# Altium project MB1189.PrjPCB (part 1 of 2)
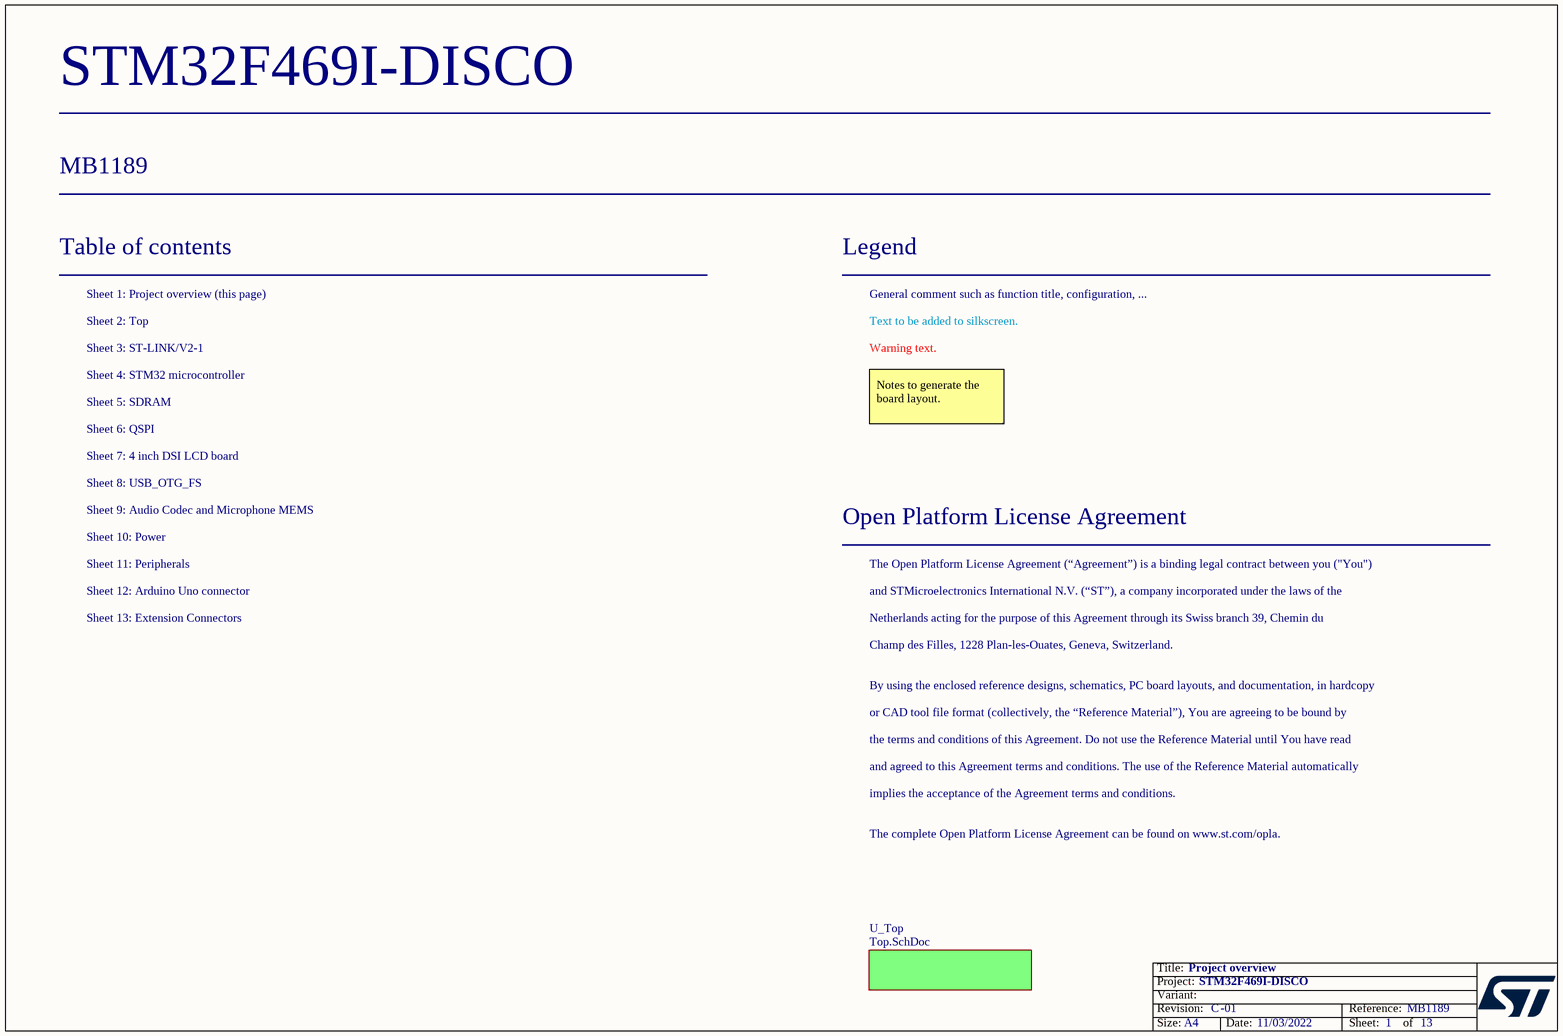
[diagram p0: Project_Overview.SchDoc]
Board_Reference: MB1189; Board_PCB_Revision: C; Board_Name: STM32F469I-DISCO; Board_Document_Date: 11/03/2022; Board_Assembly_revision: 01
13 sheets, 276 parts. Net scope: flat (ports and power ports of the same name join across sheets).
Board file: MB1189.PcbDoc
Sheets:
  Project_Overview.SchDoc
    U_Top = Top.SchDoc
      U_Memory = Memory.SchDoc
      U_Peripherals = Peripherals.SchDoc
      U_Power = Power.SchDoc
      U_ST_LINK_V2-1 = ST_LINK_V2-1.SCHDOC
      U_MCU = MCU.SchDoc
      U_Arduino_ Connectors = Arduino_ Connectors.SchDoc
      U_DSI_LCD = DSI_LCD.SchDoc
      U_QSPI = QSPI.SchDoc
      U_AUDIO2 = AUDIO2.SchDoc
      U_USB_OTG_FS = USB_OTG_FS.SchDoc
      U_ExtensionConnector = ExtensionConnector.SchDoc

## Sheet Project_Overview.SchDoc: Project overview
size A4; Date: Not used; ApprovedBy: Not used; CheckedBy: Not used; Author: Not used; CompanyName: STMicroelectronics; DrawnBy: Not used; Engineer: Not used; Organization: Not used; Address1: Not used; Address2: Not used; Address3: Not used; Address4: Not used; DocumentNumber: MB1189; Revision: Not used; SheetNumber: 1; SheetTotal: 13

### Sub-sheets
U_Top = Top.SchDoc: no entries

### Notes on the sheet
- Table of contents
- Sheet 1: Project overview (this page)
- Legend
- General comment such as function title, configuration, ...
- Sheet 2: Top
- Sheet 3: ST-LINK/V2-1
- Sheet 4: STM32 microcontroller
- Text to be added to silkscreen.
- Warning text.
- Sheet 5: SDRAM
- Sheet 6: QSPI
- Notes to generate the board layout.
- Sheet 7: 4 inch DSI LCD board
- Sheet 9: Audio Codec and Microphone MEMS
- Sheet 8: USB_OTG_FS
- Sheet 10: Power
- Sheet 11: Peripherals
- Open Platform License Agreement
- The Open Platform License Agreement (“Agreement”) is a binding legal contract between you ("You")
- Sheet 12: Arduino Uno connector
- Sheet 13: Extension Connectors
- and STMicroelectronics International N.V. (“ST”), a company incorporated under the laws of the
- Netherlands acting for the purpose of this Agreement through its Swiss branch 39, Chemin du
- Champ des Filles, 1228 Plan-les-Ouates, Geneva, Switzerland.
- By using the enclosed reference designs, schematics, PC board layouts, and documentation, in hardcopy
- or CAD tool file format (collectively, the “Reference Material”), You are agreeing to be bound by
- the terms and conditions of this Agreement. Do not use the Reference Material until You have read
- and agreed to this Agreement terms and conditions. The use of the Reference Material automatically
- implies the acceptance of the Agreement terms and conditions.
- The complete Open Platform License Agreement can be found on www.st.com/opla.

## Sheet Top.SchDoc: MB1189
size A3; Date: 9/24/2014; Author: P.A.; CompanyName: STMicroelectronics; Organization: Microcontrollers Division; Address1: 12, Rue Jules HOROWITZ; Address2: 38019 Grenoble; Address3: FRANCE; DocumentNumber: MB1189; Revision: B-07; SheetNumber: 2; SheetTotal: 13; Project: STM32F469I-DISCO
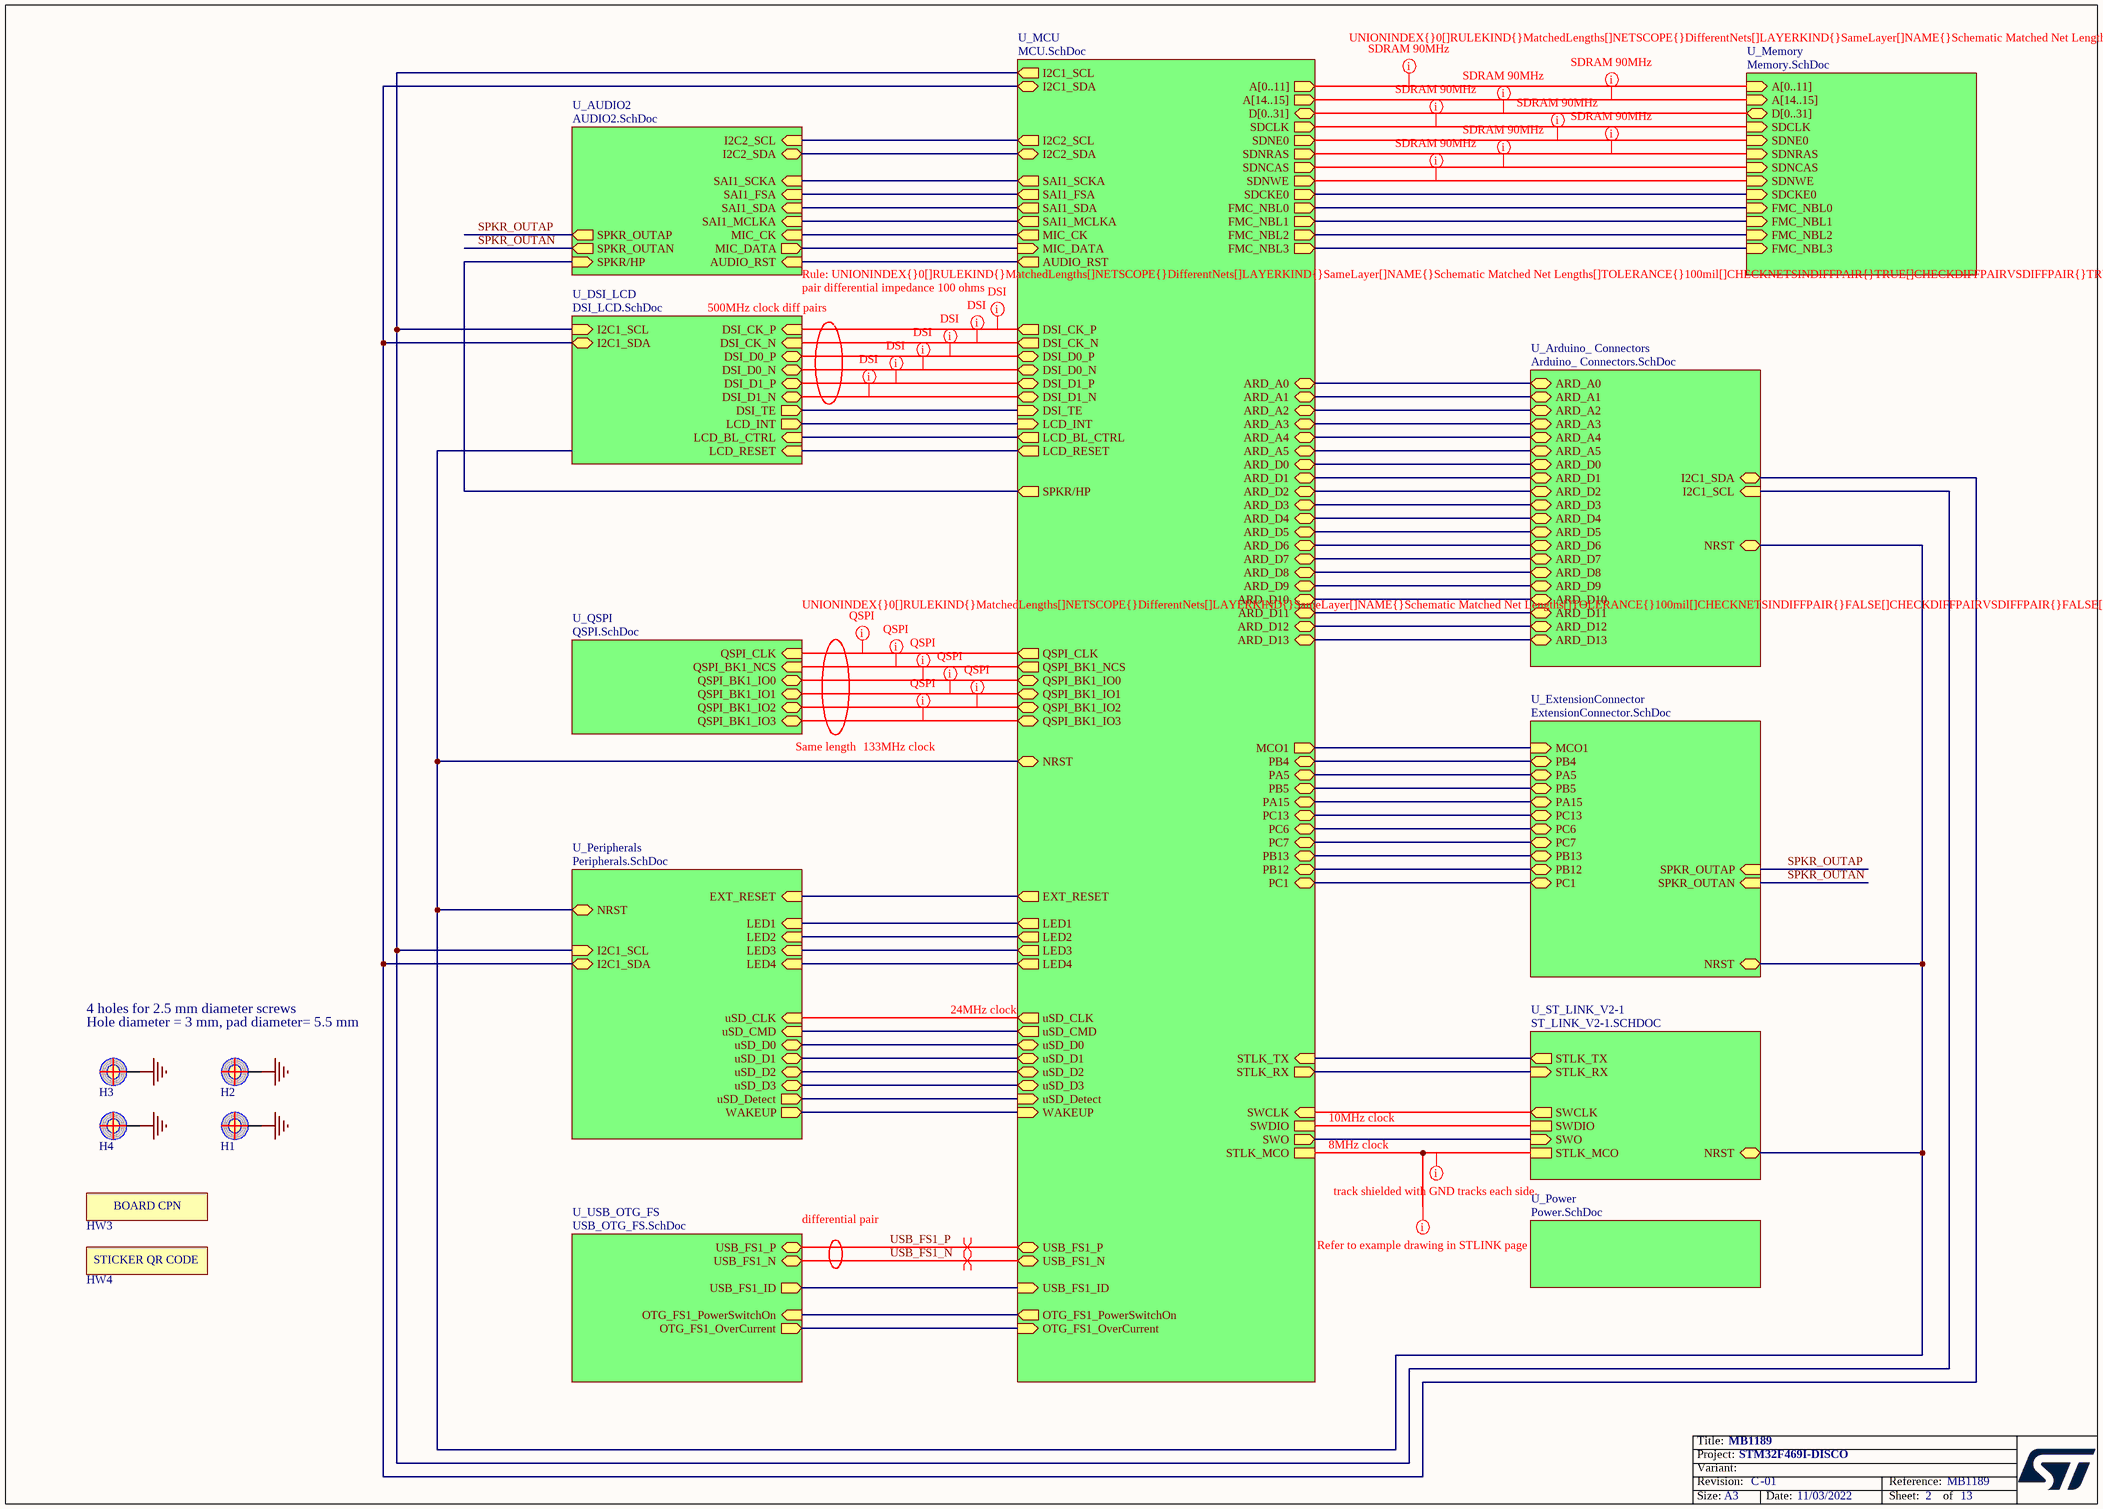
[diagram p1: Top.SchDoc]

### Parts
H1  POSITION HOLE  [HOLE_C5R5D3]  (value not drawn)
H2  POSITION HOLE  [HOLE_C5R5D3]  (value not drawn)
H3  POSITION HOLE  [HOLE_C5R5D3]  (value not drawn)
H4  POSITION HOLE  [HOLE_C5R5D3]  (value not drawn)
HW3  STICKER_BOARD_CPN  [STICKER_BOARD-CPN_13X3]  (value not drawn)  (no BOM)
HW4  STICKER_QR_CODE  [STICKER_QR_CODE_8X8]  (value not drawn)  (no BOM)

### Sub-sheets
U_Arduino_ Connectors = Arduino_ Connectors.SchDoc: I2C1_SDA (bidir), ARD_A0 (bidir), ARD_A1 (bidir), ARD_A2 (bidir), ARD_A3 (bidir), ARD_A4 (bidir), ARD_A5 (bidir), ARD_D5 (bidir), ARD_D4 (bidir), ARD_D3 (bidir), ARD_D2 (bidir), ARD_D1 (bidir), ARD_D0 (bidir), ARD_D13 (bidir), ARD_D12 (bidir), ARD_D11 (bidir), ARD_D10 (bidir), ARD_D9 (bidir), ARD_D8 (bidir), ARD_D6 (bidir), ARD_D7 (bidir), I2C1_SCL (in), NRST (bidir)
U_AUDIO2 = AUDIO2.SchDoc: SAI1_SCKA (in), SAI1_FSA (in), SAI1_SDA (in), AUDIO_RST (in), SAI1_MCLKA (in), I2C2_SCL (in), I2C2_SDA (bidir), MIC_CK (in), MIC_DATA (out), SPKR_OUTAP (out), SPKR_OUTAN (out), SPKR/HP (in)
U_DSI_LCD = DSI_LCD.SchDoc: DSI_CK_P (in), DSI_CK_N (in), DSI_D0_P (bidir), DSI_D0_N (bidir), DSI_D1_P (bidir), DSI_D1_N (bidir), DSI_TE (out), I2C1_SDA (bidir), I2C1_SCL (in), LCD_BL_CTRL (in), LCD_INT (out), LCD_RESET (in)
U_ExtensionConnector = ExtensionConnector.SchDoc: SPKR_OUTAP (in), SPKR_OUTAN (in), NRST (bidir), MCO1 (in), PB4 (bidir), PA5 (bidir), PB5 (bidir), PA15 (bidir), PC13 (bidir), PC7 (bidir), PC6 (bidir), PB13 (bidir), PB12 (bidir), PC1 (bidir)
U_MCU = MCU.SchDoc: LCD_BL_CTRL (out), MIC_CK (out), I2C1_SCL (out), I2C1_SDA (bidir), uSD_D0 (bidir), uSD_D1 (bidir), uSD_D2 (bidir), EXT_RESET (out), uSD_D3 (bidir), uSD_CLK (out), uSD_CMD (out), FMC_NBL3 (out), FMC_NBL2 (out), FMC_NBL0 (out), FMC_NBL1 (out), SAI1_SDA (out), SAI1_SCKA (out), SAI1_FSA (out), SAI1_MCLKA (out), SDNRAS (out), SDCLK (out), SDNCAS (out), SDCKE0 (out), SDNE0 (out), SDNWE (out), D[0..31] (bidir), QSPI_CLK (out), QSPI_BK1_NCS (out), QSPI_BK1_IO3 (bidir), QSPI_BK1_IO2 (bidir), QSPI_BK1_IO1 (bidir), QSPI_BK1_IO0 (bidir), WAKEUP (in), DSI_TE (in), DSI_CK_P (out), DSI_CK_N (out), DSI_D0_P (bidir), DSI_D0_N (bidir), DSI_D1_P (bidir), DSI_D1_N (bidir), NRST (bidir), LCD_INT (in), LED1 (out), LED2 (out), LED3 (out), LED4 (out), uSD_Detect (in), STLK_TX (in), STLK_RX (out), ARD_D5 (bidir), ARD_D4 (bidir), ARD_D3 (bidir), ARD_D2 (bidir), ARD_D1 (bidir), ARD_D0 (bidir), ARD_D13 (bidir), ARD_D12 (bidir), ARD_D11 (bidir), ARD_D10 (bidir), ARD_D9 (bidir), ARD_D8 (bidir), ARD_D6 (bidir), ARD_D7 (bidir), ARD_A0 (bidir), ARD_A1 (bidir), ARD_A2 (bidir), ARD_A3 (bidir), ARD_A4 (bidir), ARD_A5 (bidir), SWCLK (in), SWO (out), AUDIO_RST (out), USB_FS1_ID (in), OTG_FS1_PowerSwitchOn (out), OTG_FS1_OverCurrent (in), I2C2_SCL (out), I2C2_SDA (bidir), MIC_DATA (in), MCO1 (out), USB_FS1_N (bidir), USB_FS1_P (bidir), SWDIO, SPKR/HP (out), A[0..11] (out), A[14..15] (out), PB4 (bidir), PB5 (bidir), PA5 (bidir), PA15 (bidir), PC7 (bidir), PC6 (bidir), PC13 (bidir), PB12 (bidir), PB13 (bidir), PC1 (bidir), LCD_RESET (out), STLK_MCO
U_Memory = Memory.SchDoc: FMC_NBL0 (in), FMC_NBL1 (in), D[0..31] (bidir), SDNCAS (in), SDNWE (in), SDNRAS (in), SDNE0 (in), SDCKE0 (in), SDCLK (in), FMC_NBL3 (in), FMC_NBL2 (in), A[0..11] (in), A[14..15] (in)
U_Peripherals = Peripherals.SchDoc: uSD_CLK (in), uSD_CMD (in), uSD_D0 (bidir), uSD_D1 (bidir), uSD_D2 (bidir), uSD_D3 (bidir), WAKEUP (out), EXT_RESET (in), LED1 (in), LED2 (in), LED3 (in), LED4 (in), NRST (bidir), uSD_Detect (out), I2C1_SDA (bidir), I2C1_SCL (in)
U_Power = Power.SchDoc: no entries
U_QSPI = QSPI.SchDoc: QSPI_BK1_IO0 (bidir), QSPI_BK1_IO2 (bidir), QSPI_BK1_IO1 (bidir), QSPI_CLK (in), QSPI_BK1_NCS (in), QSPI_BK1_IO3 (bidir)
U_ST_LINK_V2-1 = ST_LINK_V2-1.SCHDOC: STLK_RX (in), STLK_TX (out), SWDIO, SWO (in), SWCLK (out), NRST (bidir), STLK_MCO
U_USB_OTG_FS = USB_OTG_FS.SchDoc: OTG_FS1_PowerSwitchOn (in), OTG_FS1_OverCurrent (out), USB_FS1_ID (out), USB_FS1_N (bidir), USB_FS1_P (bidir)

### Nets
GND: H1.1 H2.1 H3.1 H4.1
SPKR_OUTAN: sheet U_AUDIO2/SPKR_OUTAN, sheet U_ExtensionConnector/SPKR_OUTAN
SPKR_OUTAP: sheet U_AUDIO2/SPKR_OUTAP, sheet U_ExtensionConnector/SPKR_OUTAP
USB_FS1_N: sheet U_MCU/USB_FS1_N, sheet U_USB_OTG_FS/USB_FS1_N
USB_FS1_P: sheet U_MCU/USB_FS1_P, sheet U_USB_OTG_FS/USB_FS1_P
(unnamed): sheet U_Memory/FMC_NBL0, sheet U_MCU/FMC_NBL0
(unnamed): sheet U_Memory/FMC_NBL1, sheet U_MCU/FMC_NBL1  [a separate net that carries the same name]
(unnamed): sheet U_Memory/SDNCAS, sheet U_MCU/SDNCAS  [a separate net that carries the same name]
(unnamed): sheet U_Memory/SDNWE, sheet U_MCU/SDNWE  [a separate net that carries the same name]
(unnamed): sheet U_Memory/SDNRAS, sheet U_MCU/SDNRAS  [a separate net that carries the same name]
(unnamed): sheet U_Memory/SDNE0, sheet U_MCU/SDNE0  [a separate net that carries the same name]
(unnamed): sheet U_Memory/SDCKE0, sheet U_MCU/SDCKE0  [a separate net that carries the same name]
(unnamed): sheet U_Memory/SDCLK, sheet U_MCU/SDCLK  [a separate net that carries the same name]
(unnamed): sheet U_Memory/FMC_NBL3, sheet U_MCU/FMC_NBL3  [a separate net that carries the same name]
(unnamed): sheet U_Memory/FMC_NBL2, sheet U_MCU/FMC_NBL2  [a separate net that carries the same name]
(unnamed): sheet U_Peripherals/uSD_CLK, sheet U_MCU/uSD_CLK  [a separate net that carries the same name]
(unnamed): sheet U_Peripherals/uSD_CMD, sheet U_MCU/uSD_CMD  [a separate net that carries the same name]
(unnamed): sheet U_Peripherals/uSD_D0, sheet U_MCU/uSD_D0  [a separate net that carries the same name]
(unnamed): sheet U_Peripherals/uSD_D1, sheet U_MCU/uSD_D1  [a separate net that carries the same name]
(unnamed): sheet U_Peripherals/uSD_D2, sheet U_MCU/uSD_D2  [a separate net that carries the same name]
(unnamed): sheet U_Peripherals/uSD_D3, sheet U_MCU/uSD_D3  [a separate net that carries the same name]
(unnamed): sheet U_Peripherals/WAKEUP, sheet U_MCU/WAKEUP  [a separate net that carries the same name]
(unnamed): sheet U_Peripherals/EXT_RESET, sheet U_MCU/EXT_RESET  [a separate net that carries the same name]
(unnamed): sheet U_Peripherals/LED1, sheet U_MCU/LED1  [a separate net that carries the same name]
(unnamed): sheet U_Peripherals/LED2, sheet U_MCU/LED2  [a separate net that carries the same name]
(unnamed): sheet U_Peripherals/LED3, sheet U_MCU/LED3  [a separate net that carries the same name]
(unnamed): sheet U_Peripherals/LED4, sheet U_MCU/LED4  [a separate net that carries the same name]
(unnamed): sheet U_Peripherals/NRST, sheet U_ST_LINK_V2-1/NRST, sheet U_MCU/NRST, sheet U_Arduino_ Connectors/NRST, sheet U_ExtensionConnector/NRST  [a separate net that carries the same name]
(unnamed): sheet U_Peripherals/uSD_Detect, sheet U_MCU/uSD_Detect  [a separate net that carries the same name]
(unnamed): sheet U_Peripherals/I2C1_SDA, sheet U_MCU/I2C1_SDA, sheet U_Arduino_ Connectors/I2C1_SDA, sheet U_DSI_LCD/I2C1_SDA  [a separate net that carries the same name]
(unnamed): sheet U_Peripherals/I2C1_SCL, sheet U_MCU/I2C1_SCL, sheet U_Arduino_ Connectors/I2C1_SCL, sheet U_DSI_LCD/I2C1_SCL  [a separate net that carries the same name]
(unnamed): sheet U_ST_LINK_V2-1/STLK_RX, sheet U_MCU/STLK_RX  [a separate net that carries the same name]
(unnamed): sheet U_ST_LINK_V2-1/STLK_TX, sheet U_MCU/STLK_TX  [a separate net that carries the same name]
(unnamed): sheet U_ST_LINK_V2-1/SWDIO, sheet U_MCU/SWDIO  [a separate net that carries the same name]
(unnamed): sheet U_ST_LINK_V2-1/SWO, sheet U_MCU/SWO  [a separate net that carries the same name]
(unnamed): sheet U_ST_LINK_V2-1/SWCLK, sheet U_MCU/SWCLK  [a separate net that carries the same name]
(unnamed): sheet U_ST_LINK_V2-1/STLK_MCO, sheet U_MCU/STLK_MCO  [a separate net that carries the same name]
(unnamed): sheet U_MCU/LCD_BL_CTRL, sheet U_DSI_LCD/LCD_BL_CTRL  [a separate net that carries the same name]
(unnamed): sheet U_MCU/MIC_CK, sheet U_AUDIO2/MIC_CK  [a separate net that carries the same name]
(unnamed): sheet U_MCU/SAI1_SDA, sheet U_AUDIO2/SAI1_SDA  [a separate net that carries the same name]
(unnamed): sheet U_MCU/SAI1_SCKA, sheet U_AUDIO2/SAI1_SCKA  [a separate net that carries the same name]
(unnamed): sheet U_MCU/SAI1_FSA, sheet U_AUDIO2/SAI1_FSA  [a separate net that carries the same name]
(unnamed): sheet U_MCU/SAI1_MCLKA, sheet U_AUDIO2/SAI1_MCLKA  [a separate net that carries the same name]
(unnamed): sheet U_MCU/QSPI_CLK, sheet U_QSPI/QSPI_CLK  [a separate net that carries the same name]
(unnamed): sheet U_MCU/QSPI_BK1_NCS, sheet U_QSPI/QSPI_BK1_NCS  [a separate net that carries the same name]
(unnamed): sheet U_MCU/QSPI_BK1_IO3, sheet U_QSPI/QSPI_BK1_IO3  [a separate net that carries the same name]
(unnamed): sheet U_MCU/QSPI_BK1_IO2, sheet U_QSPI/QSPI_BK1_IO2  [a separate net that carries the same name]
(unnamed): sheet U_MCU/QSPI_BK1_IO1, sheet U_QSPI/QSPI_BK1_IO1  [a separate net that carries the same name]
(unnamed): sheet U_MCU/QSPI_BK1_IO0, sheet U_QSPI/QSPI_BK1_IO0  [a separate net that carries the same name]
(unnamed): sheet U_MCU/DSI_TE, sheet U_DSI_LCD/DSI_TE  [a separate net that carries the same name]
(unnamed): sheet U_MCU/DSI_CK_P, sheet U_DSI_LCD/DSI_CK_P  [a separate net that carries the same name]
(unnamed): sheet U_MCU/DSI_CK_N, sheet U_DSI_LCD/DSI_CK_N  [a separate net that carries the same name]
(unnamed): sheet U_MCU/DSI_D0_P, sheet U_DSI_LCD/DSI_D0_P  [a separate net that carries the same name]
(unnamed): sheet U_MCU/DSI_D0_N, sheet U_DSI_LCD/DSI_D0_N  [a separate net that carries the same name]
(unnamed): sheet U_MCU/DSI_D1_P, sheet U_DSI_LCD/DSI_D1_P  [a separate net that carries the same name]
(unnamed): sheet U_MCU/DSI_D1_N, sheet U_DSI_LCD/DSI_D1_N  [a separate net that carries the same name]
(unnamed): sheet U_MCU/LCD_INT, sheet U_DSI_LCD/LCD_INT  [a separate net that carries the same name]
(unnamed): sheet U_MCU/ARD_D5, sheet U_Arduino_ Connectors/ARD_D5  [a separate net that carries the same name]
(unnamed): sheet U_MCU/ARD_D4, sheet U_Arduino_ Connectors/ARD_D4  [a separate net that carries the same name]
(unnamed): sheet U_MCU/ARD_D3, sheet U_Arduino_ Connectors/ARD_D3  [a separate net that carries the same name]
(unnamed): sheet U_MCU/ARD_D2, sheet U_Arduino_ Connectors/ARD_D2  [a separate net that carries the same name]
(unnamed): sheet U_MCU/ARD_D1, sheet U_Arduino_ Connectors/ARD_D1  [a separate net that carries the same name]
(unnamed): sheet U_MCU/ARD_D0, sheet U_Arduino_ Connectors/ARD_D0  [a separate net that carries the same name]
(unnamed): sheet U_MCU/ARD_D13, sheet U_Arduino_ Connectors/ARD_D13  [a separate net that carries the same name]
(unnamed): sheet U_MCU/ARD_D12, sheet U_Arduino_ Connectors/ARD_D12  [a separate net that carries the same name]
(unnamed): sheet U_MCU/ARD_D11, sheet U_Arduino_ Connectors/ARD_D11  [a separate net that carries the same name]
(unnamed): sheet U_MCU/ARD_D10, sheet U_Arduino_ Connectors/ARD_D10  [a separate net that carries the same name]
(unnamed): sheet U_MCU/ARD_D9, sheet U_Arduino_ Connectors/ARD_D9  [a separate net that carries the same name]
(unnamed): sheet U_MCU/ARD_D8, sheet U_Arduino_ Connectors/ARD_D8  [a separate net that carries the same name]
(unnamed): sheet U_MCU/ARD_D6, sheet U_Arduino_ Connectors/ARD_D6  [a separate net that carries the same name]
(unnamed): sheet U_MCU/ARD_D7, sheet U_Arduino_ Connectors/ARD_D7  [a separate net that carries the same name]
(unnamed): sheet U_MCU/ARD_A0, sheet U_Arduino_ Connectors/ARD_A0  [a separate net that carries the same name]
(unnamed): sheet U_MCU/ARD_A1, sheet U_Arduino_ Connectors/ARD_A1  [a separate net that carries the same name]
(unnamed): sheet U_MCU/ARD_A2, sheet U_Arduino_ Connectors/ARD_A2  [a separate net that carries the same name]
(unnamed): sheet U_MCU/ARD_A3, sheet U_Arduino_ Connectors/ARD_A3  [a separate net that carries the same name]
(unnamed): sheet U_MCU/ARD_A4, sheet U_Arduino_ Connectors/ARD_A4  [a separate net that carries the same name]
(unnamed): sheet U_MCU/ARD_A5, sheet U_Arduino_ Connectors/ARD_A5  [a separate net that carries the same name]
(unnamed): sheet U_MCU/AUDIO_RST, sheet U_AUDIO2/AUDIO_RST  [a separate net that carries the same name]
(unnamed): sheet U_MCU/USB_FS1_ID, sheet U_USB_OTG_FS/USB_FS1_ID  [a separate net that carries the same name]
(unnamed): sheet U_MCU/OTG_FS1_PowerSwitchOn, sheet U_USB_OTG_FS/OTG_FS1_PowerSwitchOn  [a separate net that carries the same name]
(unnamed): sheet U_MCU/OTG_FS1_OverCurrent, sheet U_USB_OTG_FS/OTG_FS1_OverCurrent  [a separate net that carries the same name]
(unnamed): sheet U_MCU/I2C2_SCL, sheet U_AUDIO2/I2C2_SCL  [a separate net that carries the same name]
(unnamed): sheet U_MCU/I2C2_SDA, sheet U_AUDIO2/I2C2_SDA  [a separate net that carries the same name]
(unnamed): sheet U_MCU/MIC_DATA, sheet U_AUDIO2/MIC_DATA  [a separate net that carries the same name]
(unnamed): sheet U_MCU/MCO1, sheet U_ExtensionConnector/MCO1  [a separate net that carries the same name]
(unnamed): sheet U_MCU/SPKR/HP, sheet U_AUDIO2/SPKR/HP  [a separate net that carries the same name]
(unnamed): sheet U_MCU/PB4, sheet U_ExtensionConnector/PB4  [a separate net that carries the same name]
(unnamed): sheet U_MCU/PB5, sheet U_ExtensionConnector/PB5  [a separate net that carries the same name]
(unnamed): sheet U_MCU/PA5, sheet U_ExtensionConnector/PA5  [a separate net that carries the same name]
(unnamed): sheet U_MCU/PA15, sheet U_ExtensionConnector/PA15  [a separate net that carries the same name]
(unnamed): sheet U_MCU/PC7, sheet U_ExtensionConnector/PC7  [a separate net that carries the same name]
(unnamed): sheet U_MCU/PC6, sheet U_ExtensionConnector/PC6  [a separate net that carries the same name]
(unnamed): sheet U_MCU/PC13, sheet U_ExtensionConnector/PC13  [a separate net that carries the same name]
(unnamed): sheet U_MCU/PB12, sheet U_ExtensionConnector/PB12  [a separate net that carries the same name]
(unnamed): sheet U_MCU/PB13, sheet U_ExtensionConnector/PB13  [a separate net that carries the same name]
(unnamed): sheet U_MCU/PC1, sheet U_ExtensionConnector/PC1  [a separate net that carries the same name]
(unnamed): sheet U_MCU/LCD_RESET, sheet U_DSI_LCD/LCD_RESET  [a separate net that carries the same name]

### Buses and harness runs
bus sheet U_MCU/A[0..11] = sheet U_Memory/A[0..11]
bus sheet U_MCU/A[14..15] = sheet U_Memory/A[14..15]
bus sheet U_MCU/D[0..31] = sheet U_Memory/D[0..31]

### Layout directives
rule Matched Net Lengths [Tolerance = 250mil]: (no net found under the mark)
rule Matched Net Lengths [Tolerance = 100mil]; rule ? : (no net found under the mark)
rule Matched Net Lengths [Tolerance = 100mil]: (no net found under the mark)
differential pair: USB_FS1_N, USB_FS1_P
mark named track shielded with GND tracks each side.: (no net found under the mark)
mark named Refer to example drawing in STLINK page: (no net found under the mark)

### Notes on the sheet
- 500MHz clock diff pairs
- Same length
- 133MHz clock
- 4 holes for 2.5 mm diameter screws
- Hole diameter = 3 mm, pad diameter= 5.5 mm
- 24MHz clock
- 10MHz clock
- 8MHz clock
- differential pair

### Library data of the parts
H1-H4 = POSITION HOLE: Ordered by: Subcon

## Sheet Memory.SchDoc: SDRAM
size A4; Date: 9/24/2014; Author: P.A.; CompanyName: STMicroelectronics; Organization: Microcontrollers Division; Address1: 12, Rue Jules HOROWITZ; Address2: 38019 Grenoble; Address3: FRANCE; DocumentNumber: MB1189; Revision: B-07; SheetNumber: 5; SheetTotal: 13; Project: STM32F469I-DISCO
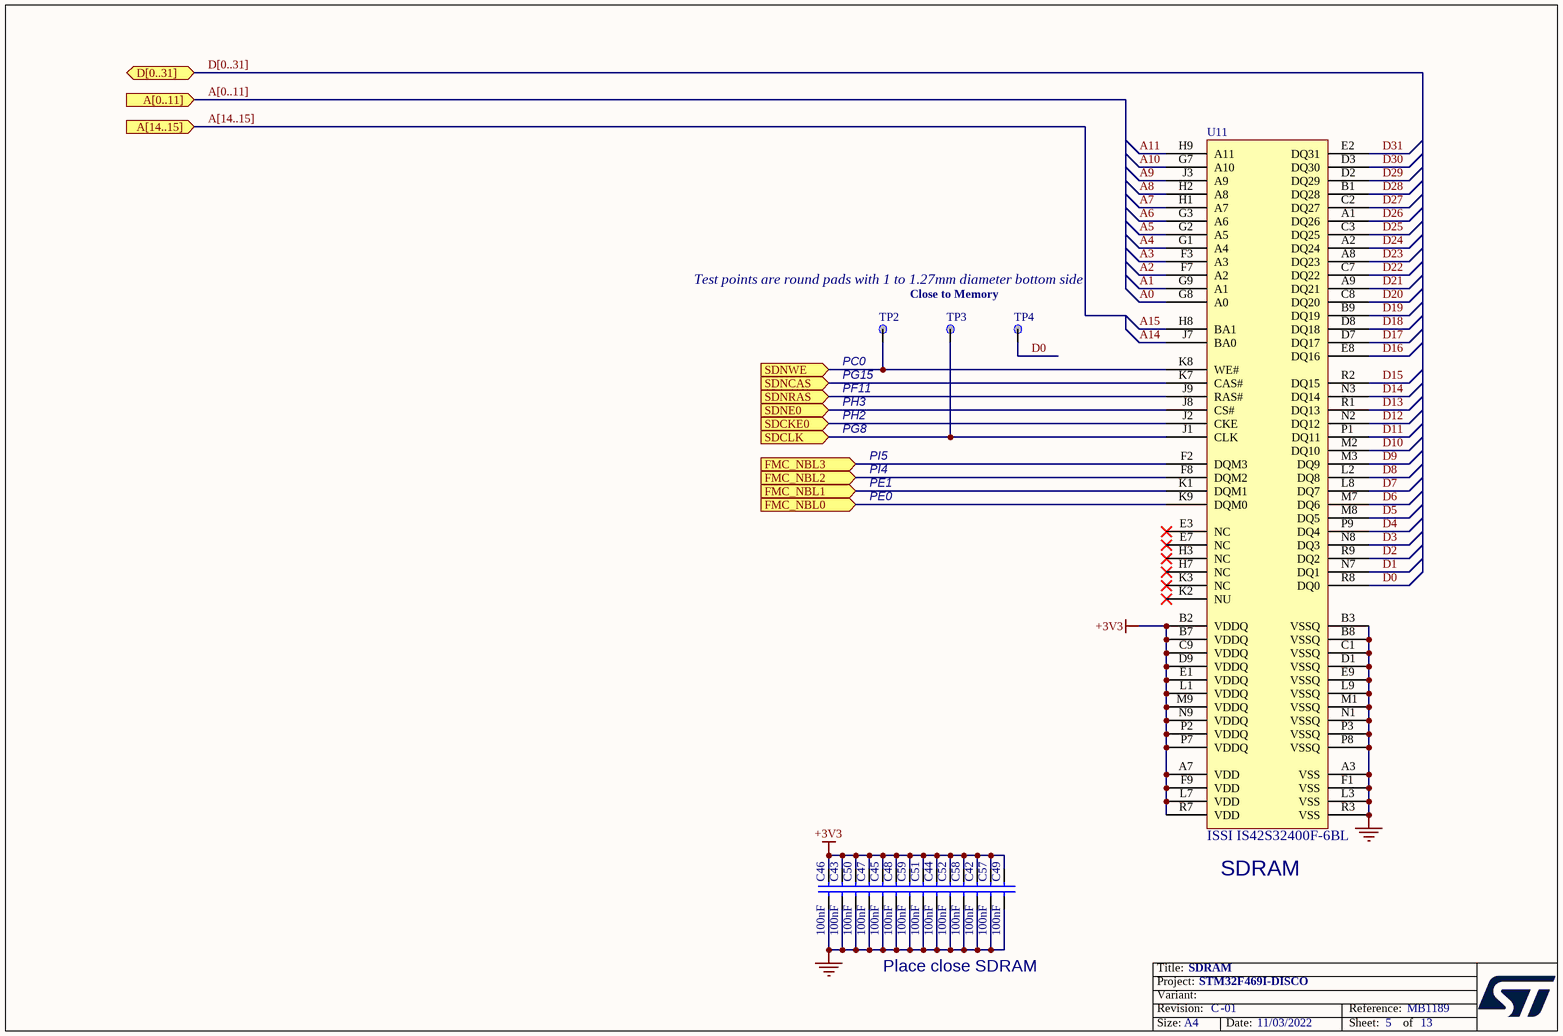
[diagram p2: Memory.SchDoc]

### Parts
C42  100nF  [0402C]
C43  100nF  [0402C]
C44  100nF  [0402C]
C45  100nF  [0402C]
C46  100nF  [0402C]
C47  100nF  [0402C]
C48  100nF  [0402C]
C49  100nF  [0402C]
C50  100nF  [0402C]
C51  100nF  [0402C]
C52  100nF  [0402C]
C57  100nF  [0402C]
C58  100nF  [0402C]
C59  100nF  [0402C]
TP2  TP  [TP_C40]  (value not drawn)
TP3  TP  [TP_C40]  (value not drawn)
TP4  TP  [TP_C40]  (value not drawn)
U11  ISSI IS42S32400F-6BL  [ICC_VFBGA90_8X13_P080]

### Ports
A[0..11] (in), A[14..15] (in), D[0..31] (bidir), FMC_NBL0 (in), FMC_NBL1 (in), FMC_NBL2 (in), FMC_NBL3 (in), SDCKE0 (in), SDCLK (in), SDNCAS (in), SDNE0 (in), SDNRAS (in), SDNWE (in)

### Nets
+3V3: C42.1 C43.1 C44.1 C45.1 C46.1 C47.1 C48.1 C49.1 C50.1 C51.1 C52.1 C57.1 C58.1 C59.1 U11.A7(VDD) U11.B2(VDDQ) U11.B7(VDDQ) U11.C9(VDDQ) U11.D9(VDDQ) U11.E1(VDDQ) U11.F9(VDD) U11.L1(VDDQ) U11.L7(VDD) U11.M9(VDDQ) U11.N9(VDDQ) U11.P2(VDDQ) U11.P7(VDDQ) U11.R7(VDD)
GND: C42.2 C43.2 C44.2 C45.2 C46.2 C47.2 C48.2 C49.2 C50.2 C51.2 C52.2 C57.2 C58.2 C59.2 U11.A3(VSS) U11.B3(VSSQ) U11.B8(VSSQ) U11.C1(VSSQ) U11.D1(VSSQ) U11.E9(VSSQ) U11.F1(VSS) U11.L3(VSS) U11.L9(VSSQ) U11.M1(VSSQ) U11.N1(VSSQ) U11.P3(VSSQ) U11.P8(VSSQ) U11.R3(VSS)
A0: U11.G8(A0)
A1: U11.G9(A1)
A2: U11.F7(A2)
A3: U11.F3(A3)
A4: U11.G1(A4)
A5: U11.G2(A5)
A6: U11.G3(A6)
A7: U11.H1(A7)
A8: U11.H2(A8)
A9: U11.J3(A9)
A10: U11.G7(A10)
A11: U11.H9(A11)
A14: U11.J7(BA0)
A15: U11.H8(BA1)
D0: TP4.1 U11.R8(DQ0)
D1: U11.N7(DQ1)
D2: U11.R9(DQ2)
D3: U11.N8(DQ3)
D4: U11.P9(DQ4)
D5: U11.M8(DQ5)
D6: U11.M7(DQ6)
D7: U11.L8(DQ7)
D8: U11.L2(DQ8)
D9: U11.M3(DQ9)
D10: U11.M2(DQ10)
D11: U11.P1(DQ11)
D12: U11.N2(DQ12)
D13: U11.R1(DQ13)
D14: U11.N3(DQ14)
D15: U11.R2(DQ15)
D16: U11.E8(DQ16)
D17: U11.D7(DQ17)
D18: U11.D8(DQ18)
D19: U11.B9(DQ19)
D20: U11.C8(DQ20)
D21: U11.A9(DQ21)
D22: U11.C7(DQ22)
D23: U11.A8(DQ23)
D24: U11.A2(DQ24)
D25: U11.C3(DQ25)
D26: U11.A1(DQ26)
D27: U11.C2(DQ27)
D28: U11.B1(DQ28)
D29: U11.D2(DQ29)
D30: U11.D3(DQ30)
D31: U11.E2(DQ31)
PC0: TP2.1 U11.K8(WE#) ; port SDNWE
PE0: U11.K9(DQM0) ; port FMC_NBL0
PE1: U11.K1(DQM1) ; port FMC_NBL1
PF11: U11.J9(RAS#) ; port SDNRAS
PG8: TP3.1 U11.J1(CLK) ; port SDCLK
PG15: U11.K7(CAS#) ; port SDNCAS
PH2: U11.J2(CKE) ; port SDCKE0
PH3: U11.J8(CS#) ; port SDNE0
PI4: U11.F8(DQM2) ; port FMC_NBL2
PI5: U11.F2(DQM3) ; port FMC_NBL3

Not connected (* = marked no-connect by the designer): U11 E3(NC)* E7(NC)* H3(NC)* H7(NC)* K2(NU)* K3(NC)*

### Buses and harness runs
bus A[0..11] = port A[0..11]
bus A[14..15] = port A[14..15]
bus D[0..31] = port D[0..31]

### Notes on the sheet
- Test points are round pads with 1 to 1.27mm diameter bottom side
- Close to Memory
- (near TP2) PC0
- (near TP2) PG15
- PF11
- PH3
- PH2
- PG8
- PE1
- PE0
- PI5
- PI4
- (near U11) SDRAM
- Place close SDRAM

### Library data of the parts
C42-C52 C57-C59 = Cap: Capacitor; Manuf_part_1: CC0402KRX7R7BB104; Manuf_1: YAGEO; Ordered by: Subcon
TP2-TP4 = TP: Ordered by: Subcon
U11 = IS42S32400F-6BL: SDRAM 128MBit 166MHZ 90BGA; Ordered by: Subcon; ECCN_US/EU: EAR99/NEC

## Sheet Peripherals.SchDoc: Peripherals
size A4; Date: 9/24/2014; Author: P.A.; CompanyName: STMicroelectronics; Organization: Microcontrollers Division; Address1: 12, Rue Jules HOROWITZ; Address2: 38019 Grenoble; Address3: FRANCE; DocumentNumber: MB1189; Revision: B-07; SheetNumber: 11; SheetTotal: 13; Project: STM32F469I-DISCO
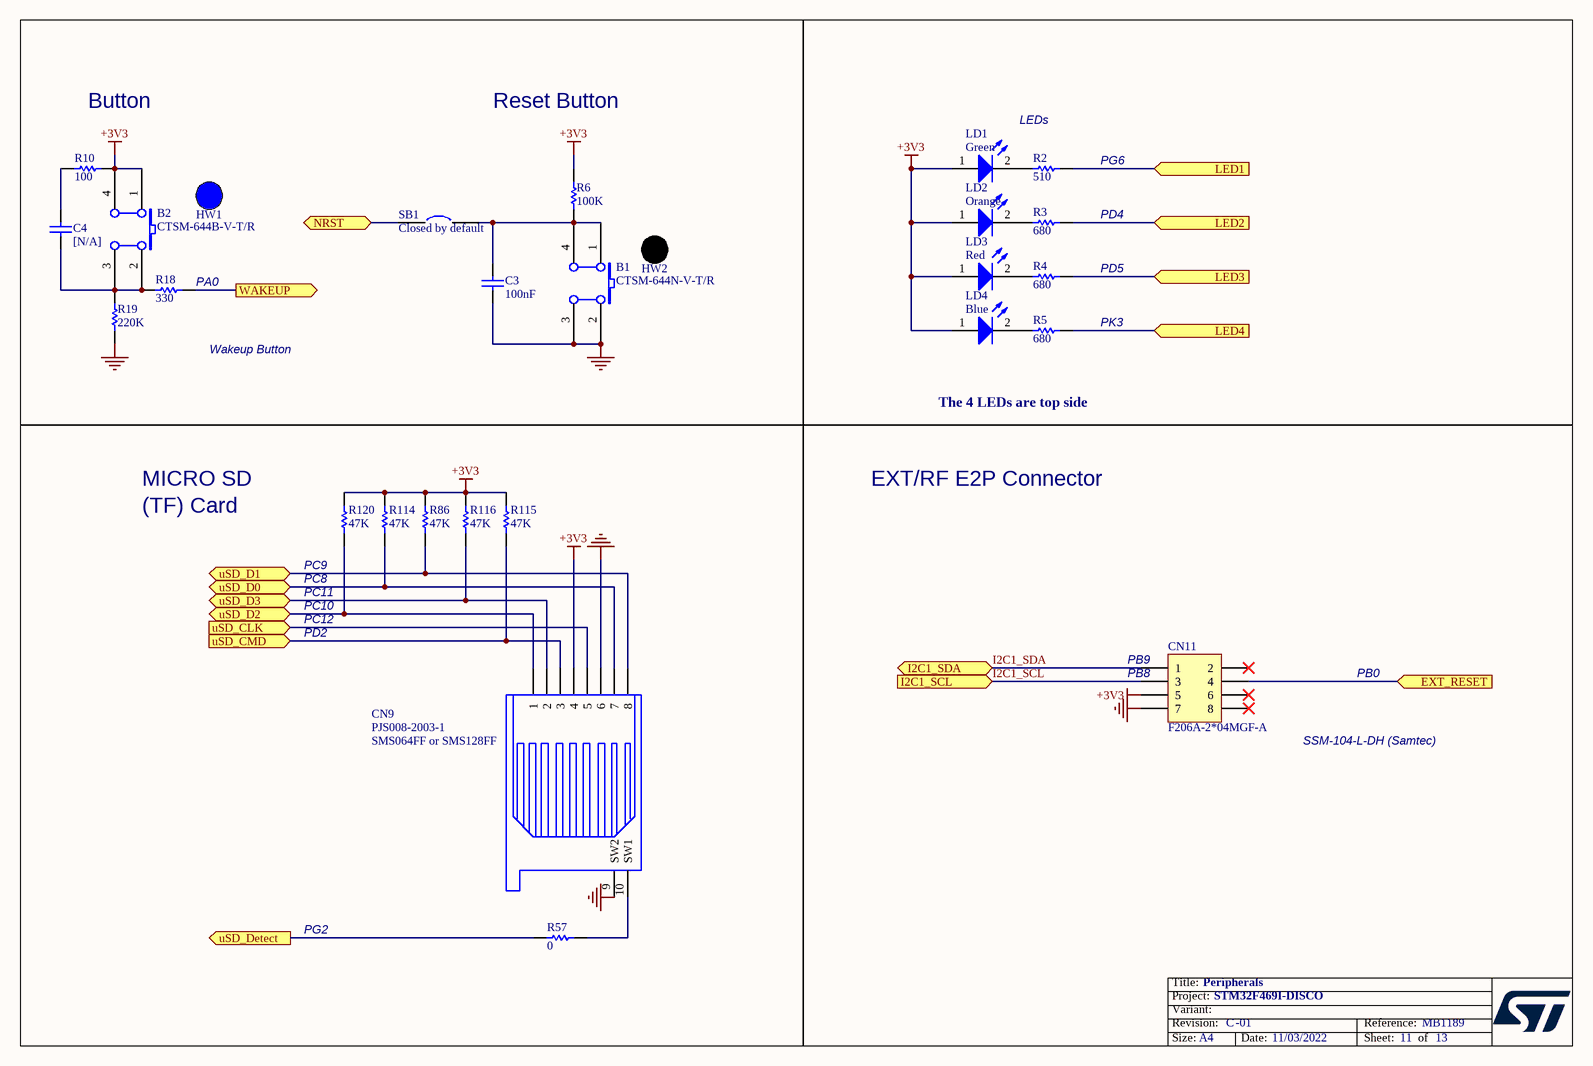
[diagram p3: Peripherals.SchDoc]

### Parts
B1  CTSM-644N-V-T/R  [PB10]
B2  CTSM-644B-V-T/R  [PB10]
C3  100nF  [0402C]
C4  [N/A]  [0603C]
CN9  PJS008-2003-1  [MSD_PJS008_]
CN11  F206A-2*04MGF-A  [SSM-104-L-DH]
HW1  BUTTON_HAT_BLUE  (value not drawn)  (mechanical)
HW2  BUTTON_HAT_BLACK  (value not drawn)  (mechanical)
LD1  Green  [0603D]
LD2  Orange  [0603D]
LD3  Red  [0603D]
LD4  Blue  [0603D]
R2  510  [0603R]
R3  680  [0603R]
R4  680  [0603R]
R5  680  [0603R]
R6  100K  [0603R]
R10  100  [0603R]
R18  330  [0603R]
R19  220K  [0603R]
R57  0  [0603R]
R86  47K  [0603R]
R114  47K  [0603R]
R115  47K  [0603R]
R116  47K  [0603R]
R120  47K  [0603R]
SB1  Closed by default  [SB_0603]

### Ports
EXT_RESET (in), I2C1_SCL (in), I2C1_SDA (bidir), LED1 (in), LED2 (in), LED3 (in), LED4 (in), NRST (bidir), uSD_CLK (in), uSD_CMD (in), uSD_D0 (bidir), uSD_D1 (bidir), uSD_D2 (bidir), uSD_D3 (bidir), uSD_Detect (out), WAKEUP (out)

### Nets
+3V3: B2.1(A0) B2.4(A1) CN9.4 CN11.5 LD1.1(A) LD2.1(A) LD3.1(A) LD4.1(A) R6.1 R10.1 R86.1 R114.1 R115.1 R116.1 R120.1
GND: B1.2(B0) B1.3(B1) C3.1 CN9.6 CN9.9(SW2) CN11.7 R19.2
I2C1_SCL: CN11.3 ; port I2C1_SCL
I2C1_SDA: CN11.1 ; port I2C1_SDA
NRST: SB1.1 ; port NRST
PA0: R18.2 ; port WAKEUP
PB0: CN11.4 ; port EXT_RESET
PC8: CN9.7 R114.2 ; port uSD_D0
PC10: CN9.1 R120.2 ; port uSD_D2
PC11: CN9.2 R116.2 ; port uSD_D3
PC12: CN9.5 ; port uSD_CLK
PD2: CN9.3 R115.2 ; port uSD_CMD
PD4: R3.1 ; port LED2
PD5: R4.1 ; port LED3
PG2: R57.1 ; port uSD_Detect
PG6: R2.1 ; port LED1
PK3: R5.1 ; port LED4
uSD_D1: CN9.8 R86.2 ; port uSD_D1
NetB1_1: B1.1(A0) B1.4(A1) C3.2 R6.2 SB1.2
NetB2_2: B2.2(B0) B2.3(B1) C4.2 R18.1 R19.1
NetC4_1: C4.1 R10.2
NetCN9_10: CN9.10(SW1) R57.2
NetLD1_2: LD1.2(K) R2.2
NetLD2_2: LD2.2(K) R3.2
NetLD3_2: LD3.2(K) R4.2
NetLD4_2: LD4.2(K) R5.2

Not connected (* = marked no-connect by the designer): CN11 2* 6* 8*

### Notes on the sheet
- Button
- Reset Button
- LEDs
- (near R2) PG6
- PD4
- (near R18) PA0
- PD5
- PK3
- Wakeup Button
- The 4 LEDs are top side
- MICRO SD
- (TF) Card
- EXT/RF E2P Connector
- (near R120) PC8
- (near R120) PC9
- PC11
- PC10
- PC12
- PD2
- (near CN11) PB9
- (near CN11) PB8
- PB0
- (near CN9) SMS064FF or SMS128FF
- (near CN11) SSM-104-L-DH (Samtec)
- PG2

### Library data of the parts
B1 = SW PUSHBUTTON: Push-Button BLACK; Manuf_1: CHAU HUA; Ordered by: Subcon; Assembly: with Blue cap; Silkscreen: USER
B2 = SW PUSHBUTTON: Push-Button BLUE; Manuf_1: CHAU HUA; Ordered by: Subcon; Assembly: with Blue cap; Silkscreen: USER
C3 = CAP: Capacitor; Manuf_part_1: CC0402KRX7R7BB104; Manuf_1: YAGEO; Ordered by: Subcon
C4 = CAP: Capacitor; Value: 100pF; Ordered by: Subcon; Fitted: NO
CN9 = SMS016AFA5E: MicroSD Card Conn, Reversed-Type, Mnt Push-Push, Positionning holes; Manuf_1: Yamaichi; Ordered by: Subcon; Silkscreen: uSD
CN11 = SSM-104-L-DH: Header, 4-Pin, Dual row; Manuf_1: SAMTEC; Ordered by: Subcon; Silkscreen: RFEEPROM
HW1 = BUTTON_HAT_BLUE: switch hat,blue; Manuf_part_1: KTSC-62B; Manuf_1: CHAU HUA
HW2 = BUTTON_HAT_BLACK: switch hat,black; Manuf_part_1: KTSC-62K; Manuf_1: CHAU HUA
LD1 = LED2: Typical RED, GREEN, YELLOW, AMBER GaAs LED; Manuf_1: Everlight Electronics; Manuf_part_1: 19-217/G7C-AN1P2/3T; Ordered by: Subcon; ECCN_US/EU: EAR99/NEC
LD2 = LED2: Typical RED, GREEN, YELLOW, AMBER GaAs LED; Manuf_1: Everlight Electronics; Manuf_part_1: 19-217/S2C-AM2N2VY/3T; Ordered by: Subcon; ECCN_US/EU: EAR99/NEC
LD3 = LED2: Typical RED, GREEN, YELLOW, AMBER GaAs LED; Manuf_1: Everlight Electronics; Manuf_part_1: 19-217/R6C-AL1M2VY/3T; Ordered by: Subcon; ECCN_US/EU: EAR99/NEC
LD4 = LED2: Typical RED, GREEN, YELLOW, AMBER GaAs LED; Manuf_1: Everlight Electronics; Manuf_part_1: 19-217/BHC-ZL1M2RY/3T; Ordered by: Subcon; ECCN_US/EU: EAR99/NEC
R2 = Res1: Resistor; Manuf_1: YAGEO; Manuf_part_1: RC0603FR-07510RL; Ordered by: Subcon
R3-R5 = Res1: Resistor; Manuf_1: YAGEO; Manuf_part_1: RC0603FR-07680RL; Ordered by: Subcon
R6 = res1: Resistor; Manuf_1: YAGEO; Manuf_part_1: RC0603FR-07100KL; Ordered by: Subcon
R10 = Res1: Resistor; Manuf_1: YAGEO; Manuf_part_1: RC0603FR-07100RL; Ordered by: Subcon
R18 = Res1: Resistor; Manuf_1: YAGEO; Manuf_part_1: RC0603FR-07330RL; Ordered by: Subcon
R19 = res1: Resistor; Manuf_1: YAGEO; Manuf_part_1: RC0603FR-07220KL; Ordered by: Subcon
R57 = Res1: Resistor; Manuf_1: YAGEO; Manuf_part_1: RC0603JR-070RL; Ordered by: Subcon
R86 R114-R116 R120 = res1: Resistor; Manuf_1: YAGEO; Manuf_part_1: RC0603FR-0747KL; Ordered by: Subcon
SB1 = Circuit Breaker: Ordered by: Subcon; Comments: Solder bridge

## Sheet Power.SchDoc: Power
size A4; Date: 9/24/2014; Author: P.A.; CompanyName: STMicroelectronics; Organization: Microcontrollers Division; Address1: 12, Rue Jules HOROWITZ; Address2: 38019 Grenoble; Address3: FRANCE; DocumentNumber: MB1189; Revision: B-07; SheetNumber: 10; SheetTotal: 13; Project: STM32F469I-DISCO
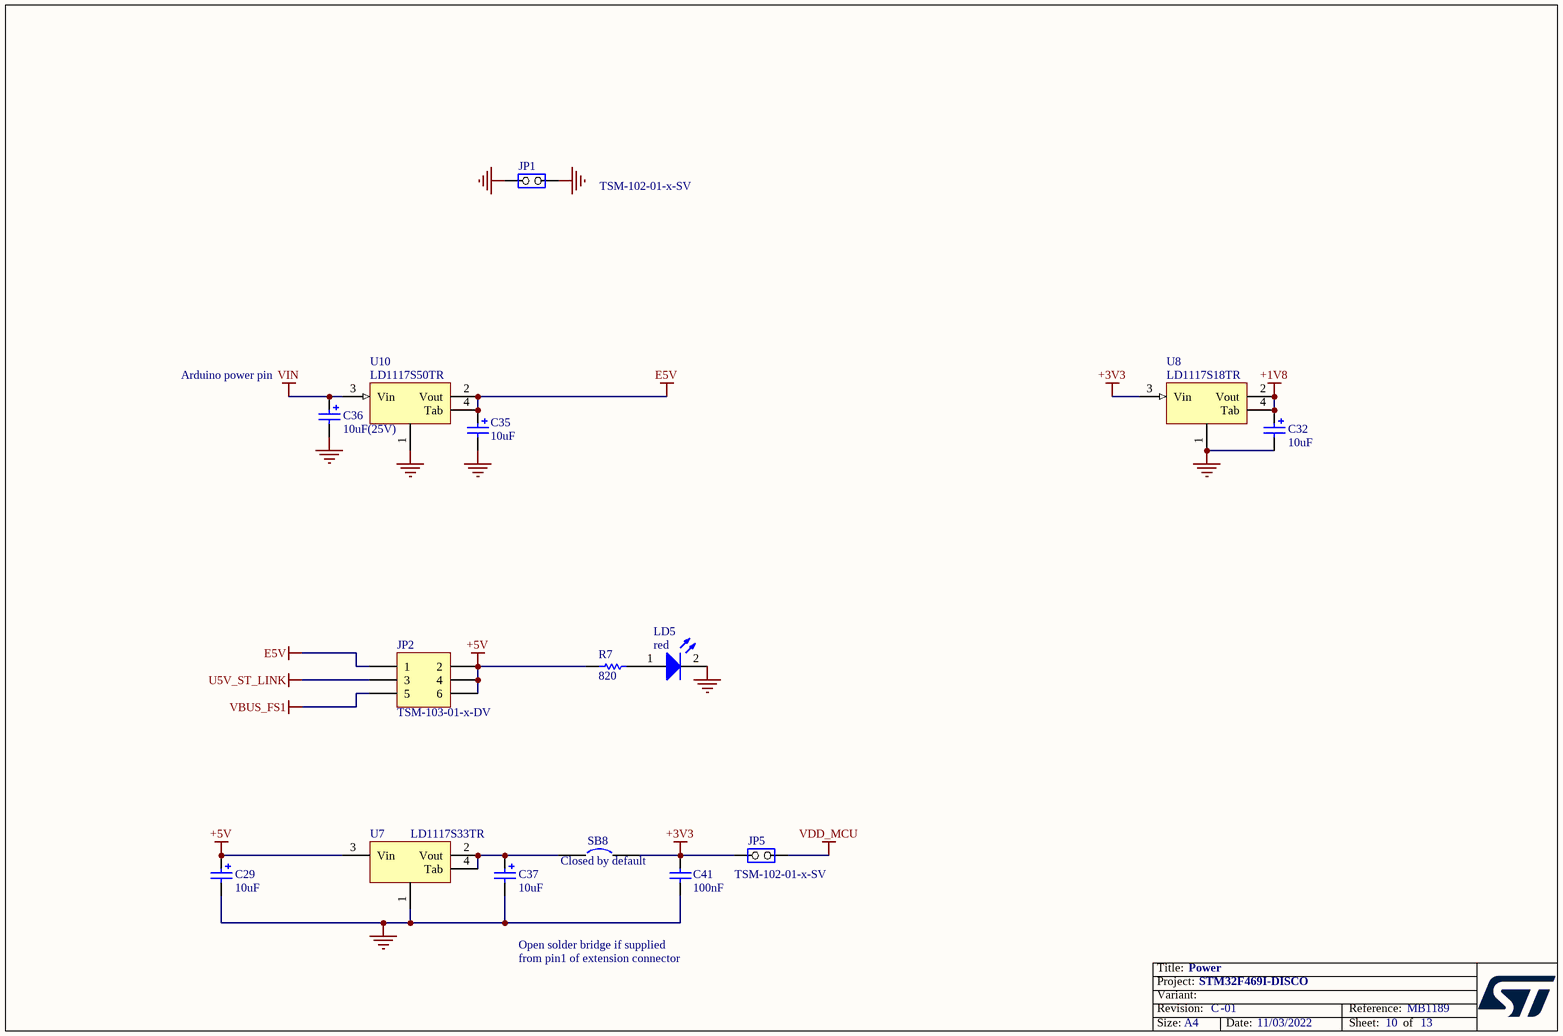
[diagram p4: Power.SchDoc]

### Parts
C29  10uF  [CPOL_TAJ-A_1206_H180]
C32  10uF  [CPOL_TAJ-A_1206_H180]
C35  10uF  [CPOL_TAJ-A_1206_H180]
C36  10uF(25V)  [CPOL_TAJ-B_1210_H210]
C37  10uF  [CPOL_TAJ-A_1206_H180]
C41  100nF  [0402C]
JP1  TSM-102-01-x-SV  [TSM-102-01-x-SV]
JP2  TSM-103-01-x-DV  [TSM-103-01-x-DV]
JP5  TSM-102-01-x-SV  [TSM-102-01-x-SV]
LD5  red  [0603D]
R7  820  [0603R]
SB8  Closed by default  [SB_0603]
U7  LD1117S33TR  [SOT-223]
U8  LD1117S18TR  [SOT-223]
U10  LD1117S50TR  [SOT-223]

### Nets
+1V8: C32.1 U8.2(Vout) U8.4(Tab)
+3V3: C41.1 JP5.1(COMMON) SB8.2 U8.3(Vin)
+5V: C29.1 JP2.2 JP2.4 JP2.6 R7.2 U7.3(Vin)
E5V: C35.1 JP2.1 U10.2(Vout) U10.4(Tab)
GND: C29.2 C32.2 C35.2 C36.2 C37.2 C41.2 JP1.1(COMMON) JP1.2(NO) LD5.2(K) U7.1 U8.1 U10.1
U5V_ST_LINK: JP2.3
VBUS_FS1: JP2.5
VDD_MCU: JP5.2(NO)
VIN: C36.1 U10.3(Vin)
NetC37_1: C37.1 SB8.1 U7.2(Vout) U7.4(Tab)
NetLD5_1: LD5.1(A) R7.1

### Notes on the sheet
- (near C36) Arduino power pin
- Open solder bridge if supplied
  from pin1 of extension connector

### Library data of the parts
C29 = Cap_TAJA106K016R: Capacitor, Tantalum, 10uF, 16V, 10%, 3Ohms, pkg Type_A (3216 metric), T=1.6mm; Manuf_1: AVX; Value: 10uF (16v)
C32 C35 C37 = Cap_TAJA106K016R: Capacitor, Tantalum, 10uF, 16V, 10%, 3Ohms, pkg Type_A (3216 metric), T=1.6mm; Manuf_1: AVX; Value: 10uF (16V)
C36 = Cap_TAJB106K025RNJ: Capacitor, Tantalum, 10uF, 25V, 10%, 2.5ohms, pkg Type_B (3528 metric), T=1.9mm; Manuf_1: AVX
C41 = Cap: as C42 on sheet Memory
JP1 = JP2: Manuf_1: SAMTEC; Ordered by: Subcon; Silkscreen: GND; Assembly: with jumper
JP2 = Header 3X2: Header, 3-Pin, Dual row; Manuf_1: SAMTEC; Ordered by: Subcon; Silkscreen: E5V:pins1,2 STLK: pins3,4 USB: pins 5,6; Assembly: 3,4 closed
JP5 = JP2: Manuf_1: SAMTEC; Ordered by: Subcon; Assembly: with jumper; Silkscreen: IDD
LD5 = LED2: Typical RED, GREEN, YELLOW, AMBER GaAs LED; Manuf_1: Everlight Electronics; Manuf_part_1: 19-217/R6C-AL1M2VY/3T; Ordered by: Subcon; ECCN_US/EU: EAR99/NEC; Silkscreen: 5V
R7 = res1: Resistor; Manuf_1: YAGEO; Manuf_part_1: RC0603FR-07820RL; Ordered by: Subcon
SB8 = Circuit Breaker: as SB1 on sheet Peripherals
U7 = LD1117S33TR: LOW DROP FIXED AND ADJUSTABLE POSITIVE VOLTAGE REGULATORS (3.3 Volts); Provided: ST; ECCN_US/EU: EAR99/NEC; Ref St: 9176186
U8 = LD1117: Ordered by: ST; ECCN_US/EU: EAR99/NEC; Ref St: 9176180
U10 = LD1117: Ordered by: ST; ECCN_US/EU: EAR99/NEC; Ref St: 9176133

## Sheet ST_LINK_V2-1.SCHDOC: ST-LINK/V2-1
size A4; Date: 9/24/2014; Author: P.A.; CompanyName: STMicroelectronics; Organization: Microcontrollers Division; Address1: 12, Rue Jules HOROWITZ; Address2: 38019 Grenoble; Address3: FRANCE; DocumentNumber: MB1189; Revision: B-07; SheetNumber: 3; SheetTotal: 13; Project: STM32F469I-DISCO
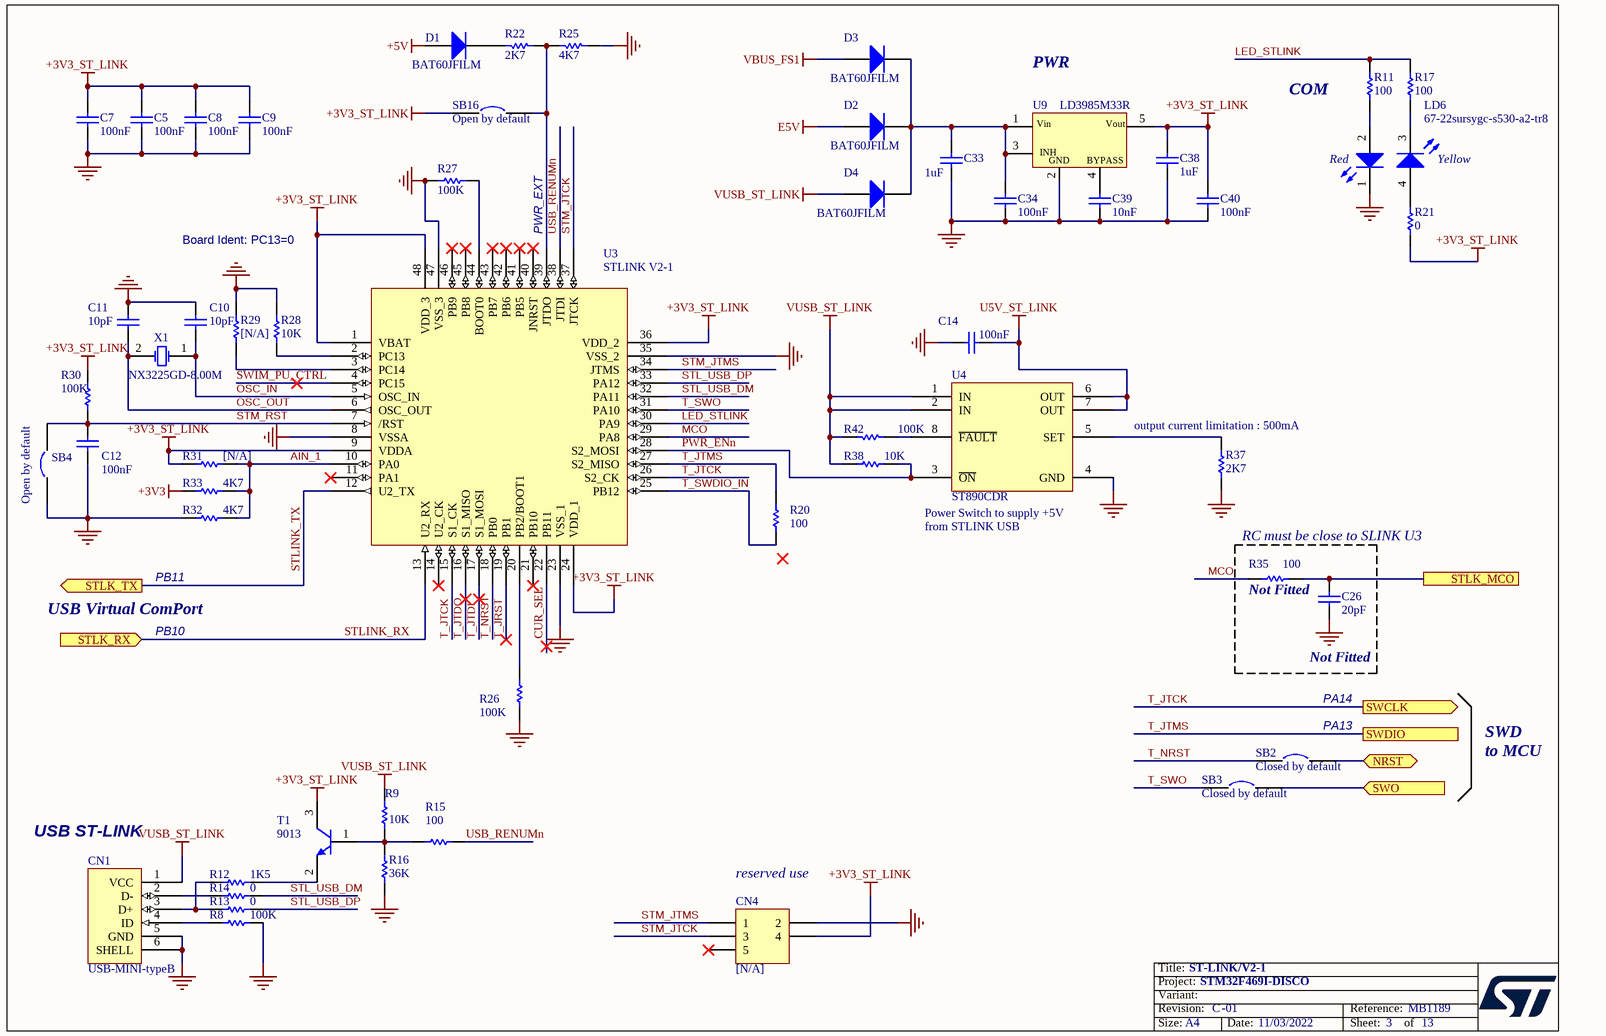
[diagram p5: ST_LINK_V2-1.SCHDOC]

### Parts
C5  100nF  [0402C]
C7  100nF  [0402C]
C8  100nF  [0402C]
C9  100nF  [0402C]
C10  10pF  [0603C]
C11  10pF  [0603C]
C12  100nF  [0402C]
C14  100nF  [0402C]
C26  20pF  [0603C]
C33  1uF  [0603C]
C34  100nF  [0402C]
C38  1uF  [0603C]
C39  10nF  [0603C]
C40  100nF  [0402C]
CN1  USB-MINI-typeB  [MINIUSB_AB_5SM_RA]
CN4  [N/A]  [HDR_2X3-1_2R54-6]
D1  BAT60JFILM  [SOD-323]
D2  BAT60JFILM  [SOD-323]
D3  BAT60JFILM  [SOD-323]
D4  BAT60JFILM  [SOD-323]
LD6  67-22sursygc-s530-a2-tr8  [LED2_3528]
R8  100K  [0603R]
R9  10K  [0402R]
R11  100  [0603R]
R12  1K5  [0603R]
R13  0  [0603R]
R14  0  [0603R]
R15  100  [0603R]
R16  36K  [0603R]
R17  100  [0603R]
R20  100  [0603R]
R21  0  [0603R]
R22  2K7  [0603R]
R25  4K7  [0603R]
R26  100K  [0603R]
R27  100K  [0603R]
R28  10K  [0402R]
R29  [N/A]  [0603R]
R30  100K  [0603R]
R31  [N/A]  [0603R]
R32  4K7  [0603R]
R33  4K7  [0603R]
R35  100  [0603R]
R37  2K7  [0603R]
R38  10K  [0402R]
R42  100K  [0603R]
SB2  Closed by default  [SB_0603]
SB3  Closed by default  [SB_0603]
SB4  Open by default  [SB_0603]
SB16  Open by default  [SB_0603]
T1  9013  [SOT-23]
U3  STLINK V2-1  [LQFP48_0R5_9X9]
U4  ST890CDR  [SOIC8_1R27_4R9X6]
U9  LD3985M33R  [SOT23-5]
X1  NX3225GD-8.00M  [XTAL_2SM_3R2X2R5_H1]

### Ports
NRST (bidir), STLK_MCO, STLK_RX (in), STLK_TX (out), SWCLK (out), SWDIO, SWO (in)

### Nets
+3V3: R33.1
+3V3_ST_LINK: C5.2 C7.2 C8.2 C9.2 C38.1 C40.2 CN4.4 R21.2 R30.2 R31.1 SB16.1 T1.3(C) U3.1(VBAT) U3.9(VDDA) U3.24(VDD_1) U3.36(VDD_2) U3.48(VDD_3) U9.5(Vout)
+5V: D1.1(A)
E5V: D2.1(A)
GND: C5.1 C7.1 C8.1 C9.1 C10.2 C11.2 C12.1 C14.1 C26.2 C33.1 C34.1 C38.2 C39.1 C40.1 CN1.5(GND) CN1.6(SHELL) CN4.2 LD6.1(RED_cathode) R8.2 R16.1 R25.2 R26.1 R27.1 R28.1 R29.1 R32.1 R37.2 SB4.1 U3.8(VSSA) U3.23(VSS_1) U3.35(VSS_2) U3.47(VSS_3) U4.4(GND) U9.2(GND)
U5V_ST_LINK: C14.2 U4.6(OUT) U4.7(OUT)
VBUS_FS1: D3.1(A)
VUSB_ST_LINK: CN1.1(VCC) D4.1(A) R9.2 R38.1 R42.1 U4.1(IN) U4.2(IN)
AIN_1: R31.2 R32.2 R33.2 U3.10(PA0)
CUR_SEL: U3.22(PB11)
LED_STLINK: R11.1 R17.1 U3.30(PA9)
MCO: R35.1 U3.29(PA8)
NRST: SB2.2 ; port NRST
OSC_IN: C10.1 U3.5(OSC_IN) X1.1(OSC1)
OSC_OUT: C11.1 U3.6(OSC_OUT) X1.2(OSC2)
PWR_ENn: R38.2 U3.28(S2_MOSI) U4.3(~{ON})
STL_USB_DM: R14.2 U3.32(PA11)
STL_USB_DP: R13.2 U3.33(PA12)
STLINK_RX: U3.13(U2_RX) ; port STLK_RX  [project net PB10]
STLINK_TX: U3.12(U2_TX) ; port STLK_TX  [project net PB11]
STLK_MCO: C26.1 R35.2 ; port STLK_MCO
STM_JTCK: CN4.3 U3.37(JTCK)
STM_JTMS: CN4.1 U3.34(JTMS)
STM_RST: C12.2 R30.1 SB4.2 U3.7(/RST)
SWIM_PU_CTRL: U3.4(PC15)
SWO: SB3.2 ; port SWO
T_JRST: U3.19(PB1)
T_JTCK: U3.15(S1_CK) U3.26(S2_CK) ; port SWCLK  [project net PA14]
T_JTDI: U3.17(S1_MOSI)
T_JTDO: U3.16(S1_MISO)
T_JTMS: R20.2 U3.27(S2_MISO) ; port SWDIO  [project net PA13]
T_NRST: SB2.1 U3.18(PB0)
T_SWDIO_IN: R20.1 U3.25(PB12)
T_SWO: SB3.1 U3.31(PA10)
USB_RENUMn: R15.2 U3.38(JTDI)
NetC33_2: C33.2 C34.2 D2.2(K) D3.2(K) D4.2(K) U9.1(Vin) U9.3(CE)
NetC39_2: C39.2 U9.4(BYPASS)
NetCN1_2: CN1.2(D-) R14.1
NetCN1_3: CN1.3(D+) R12.1 R13.1
NetCN1_4: CN1.4(ID) R8.1
NetD1_2: D1.2(K) R22.1
NetLD6_2: LD6.2(Red_anode) R11.2
NetLD6_3: LD6.3(YellowGreen_cathode) R17.2
NetLD6_4: LD6.4(YellowGreen_anode) R21.1
NetR9_1: R9.1 R15.1 R16.2 T1.1(B)
NetR12_2: R12.2 T1.2(E)
NetR22_2: R22.2 R25.1 SB16.2 U3.39(JTDO)
NetR26_2: R26.2 U3.20(PB2/BOOT1)
NetR27_2: R27.2 U3.44(BOOT0)
NetR28_2: R28.2 U3.2(PC13)
NetR29_2: R29.2 U3.3(PC14)
NetR37_1: R37.1 U4.5(SET)
NetR42_2: R42.2 U4.8(~{FAULT})

Not connected (* = marked no-connect by the designer): CN4 5*; U3 11(PA1)* 14(U2_CK)* 21(PB10)* 40(JNRST)* 41(PB5)* 42(PB6)* 43(PB7)* 45(PB8)* 46(PB9)*

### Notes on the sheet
- PWR
- COM
- Board Ident: PC13=0
- PWR_EXT
- (near R37) output current limitation : 500mA
- PB11
- (near U4) Power Switch to supply +5V from STLINK USB
- RC must be close to SLINK U3
- USB Virtual ComPort
- PB10
- Not Fitted
- (near C26) Not Fitted
- PA14
- (near SB2) PA13
- SWD
  to MCU
- (near CN1) USB ST-LINK
- (near CN4) reserved use

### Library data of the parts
C5 C7-C9 C12 C14 C34 C40 = Capacitor_ST: Capacitor 0402 / 0603 / 0805; Manuf_part_1: CC0402KRX7R7BB104; Manuf_1: YAGEO; Ordered by: Subcon
C10 = Capacitor_ST: Capacitor 0402 / 0603 / 0805; Manuf_1: YAGEO; Manuf_part_1: CC0603JRNPO9BN100; Ordered by: Subcon
C11 = Capacitor_ST: Capacitor 0402 / 0603 / 0805; Manuf_part_1: CC0603JRNPO9BN100; Manuf_1: YAGEO; Ordered by: Subcon
C26 = Cap_20pF_NPO_5%_0402: Capacitor,20pF,50V,NPO,5%,0402,YAGEO; Order: CC0402JRNPO9BN200; Fitted: NO; Ordered by: Subcon
C33 C38 = CAP SMD 0603  X5R 1µF 25V 10%: Capacitor; Manuf_1: YAGEO; Manuf_part_1: CC0603KRX5R7BB105; Rated voltage: 25V; Tolerance: 10%; Ordered by: Subcon
C39 = CAP SMD 0603  X7R 10000PF 50V 10%: 0603  X7R 10NF; Manuf_1: YAGEO; Manuf_part_1: CC0603KRX7R9BB103; Order code RS: 2040779; Rated voltage: 50V; Tolerance: 10%; Ordered by: Subcon
CN1 = USB-MINI-typeB connector: Manuf_Part_1: 5075BMR-05-SM; Manuf_1: NELTRON; Ordered by: Subcon; Silkscreen: USB ST-LINK
CN4 = Header 3X2: Header, 3-Pin, Dual row; Fitted: NO; Ordered by: Subcon
D1-D4 = BAT60JFILM: Provided: ST; ECCN_US/EU: EAR99/NEC; Ref St: 9151097
LD6 = HSMF-A201-A00J1: Manuf_1: EVERLIGHT; Ordered by: Subcon
R8 = res1: as R6 on sheet Peripherals
R9 = Res1: Resistor; Manuf_1: YAGEO; Manuf_part_1: RC0402FR-0710KL; Ordered by: Subcon
R11 R17 = Res1: as R10 on sheet Peripherals
R12 = Resistor_ST: Resistor; Manuf_1: YAGEO; MAnuf_part_1: RC0603FR-071K5L; Ordered by: Subcon
R13 R14 = Resistor_ST: Resistor; Manuf_1: YAGEO; Manuf_part_1: RC0603JR-070RL; Ordered by: Subcon
R15 R35 = Resistor_ST: Resistor 0402 / 0603 / 0805; Manuf_1: YAGEO; Manuf_part_1: RC0603FR-07100RL; Ordered by: Subcon
R16 = Res1: Resistor; Manuf_1: YAGEO; Manuf_part_1: RC0603FR-0736KL; Ordered by: Subcon
R20 = Resistor_ST: Resistor; Manuf_1: YAGEO; Manuf_part_1: RC0603FR-07100RL; Ordered by: Subcon
R21 = Res1: as R57 on sheet Peripherals
R22 = Res1: Resistor; Manuf_1: YAGEO; Manuf_part_1: RC0603FR-072K7L; Ordered by: Subcon
R25 = Res1: Resistor; Manuf_1: YAGEO; Manuf_part_1: RC0603FR-074K7L; Ordered by: Subcon
R26 R27 R30 = Resistor_ST: Resistor 0402 / 0603 / 0805; Manuf_1: YAGEO; Manuf_part_1: RC0603FR-07100KL; Ordered by: Subcon
R28 R38 = Resistor_ST: Resistor; Manuf_1: YAGEO; Manuf_part_1: RC0402FR-0710KL; Ordered by: Subcon
R29 R31 = Resistor_ST: Resistor 0402 / 0603 / 0805; Value: 10K; Fitted: NO; Ordered by: Subcon
R32 R33 = Resistor_ST: Resistor 0402 / 0603 / 0805; Manuf_1: YAGEO; Manuf_part_1: RC0603FR-074K7L; Ordered by: Subcon
R37 = Resistor_ST: Resistor 0402 / 0603 / 0805; Manuf_1: YAGEO; Manuf_part_1: RC0603FR-072K7L; Ordered by: Subcon
R42 = Res1: Resistor; Manuf_1: YAGEO; Manuf_part_1: RC0603FR-07100KL; Ordered by: Subcon
SB2 SB3 = Circuit Breaker: as SB1 on sheet Peripherals
SB4 SB16 = Circuit Breaker: Ordered by: Subcon; Comments: Solder bridge; Solder: NO
T1 = NPN: NPN Bipolar Transistor; Manuf_Part_1: MMBT9013; Code - JEDEC: TO-226-AA; Ordered by: Subcon; ECCN_US/EU: EAR99/NEC
U3 = STM32F10x(48pin): Manuf_Part_1: STM32F103CBT6; Ordered by: ST; ECCN_US/EU: 3A991A2/NEC; Ref St: 9175111
U4 = ST890CDR: Ordered by: ST; Ref St: 9172002; ECCN_US/EU: EAR99/NEC
U9 = LD3985M33R: Ultra low drop-low noise BiCMOS voltage, regulators low ESR capacitors compatible; Manuf_1: ST; Ref St: 9176161; ECCN_US/EU: EAR99/NEC
X1 = XTAL_8M_NX3225GD: Crystal 8Mhz, 8pF, -+50PPM, SMD; Manuf_1: NDK; Manuf_Part_1: NX3225GD 8MHz EXS00A-CG04874; Manuf_Part_2: NX3225GD-8.000M-STD-CRA-3; ECCN_US/EU: EAR99/NEC; NDK Ref: X3127326; Ref St: 9157029; Provided: ST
